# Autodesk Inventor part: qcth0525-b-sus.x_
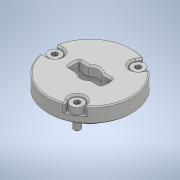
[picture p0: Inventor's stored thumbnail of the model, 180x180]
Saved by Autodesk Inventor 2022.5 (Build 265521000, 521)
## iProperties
Part Number: qcth0525-b-sus.x_
Material: 一般
Document SubType Name: Modeling
Designer: ImaoCorp
Density: 1 g/cm^3
Appearance: 既定
Sending System: SOLIDWORKS 2017-2017317
MC: AMD64
MC_MODEL: Intel64 Family 6 Model 60 Stepping 3, GenuineIntel
OS: Windows_NT
FRU: Parasolid Version 29.0, build 201,  4-17-2017
FORMAT: text
GUISE: transmit
KEY: qcth0525-b-sus
FILE: qcth0525-b-sus.x_t
DATE: Wed Sep 04 15:22:41 2019
Author: ImaoCorp
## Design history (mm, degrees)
feature "Base1"
node "ソリッド1"
